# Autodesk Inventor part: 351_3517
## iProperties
Author: tomm
Created: 2002-01
Part Number: 351_3517
Material: Nylon-6/6
Document SubType Name: Modeling
Designer: tomm
Category: part
Company: Slidell Inc.
Control State: 0
Master: False
Checked Out: False
Last Check In By: tomm
Last Check In Date: 2002-01-29
PropertySet Name: Design Tracking Control
Shininess: 24.0
PropertySet Name: _Private Model Information
Density: 1.13
Volumn: 7.147063483076227
Area: 57.844297252666166
PropertySet Name: Model Information
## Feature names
1. Extrusion1
2. Fillet1
3. Fillet2
4. Shell1
5. Fillet3
6. Extrusion2
7. Fillet4
8. Fillet5
9. Fillet6
